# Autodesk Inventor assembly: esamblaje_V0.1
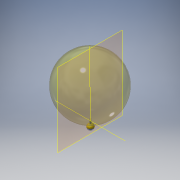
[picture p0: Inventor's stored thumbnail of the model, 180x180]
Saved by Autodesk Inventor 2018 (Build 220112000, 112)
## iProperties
Created: 2018-09
Part Number: esamblaje_V0.1
Document SubType Name: Assembly
Designer: Gordillo
Author: Gordillo
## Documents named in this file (3)
- D:\ownCloud\SmartOpenLab\Proyectos\DirigiblesSOL\Diseño3D\esamblaje_V0.1.iam
- D:\ownCloud\SmartOpenLab\Proyectos\DirigiblesSOL\Diseño3D\globo_helio_mediano_V0.1.ipt
- D:\ownCloud\SmartOpenLab\Proyectos\DirigiblesSOL\Diseño3D\caja_interna_V0.2.ipt
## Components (2 placed, 2 different names)
1. globo_helio_mediano_V0.1:1 — Mate:1, Mate:2, Mate:3
2. caja_interna_V0.2:1
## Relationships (3: Mate 3)
- Mate:1: globo_helio_mediano_V0.1:1
- Mate:2: globo_helio_mediano_V0.1:1
- Mate:3: globo_helio_mediano_V0.1:1
